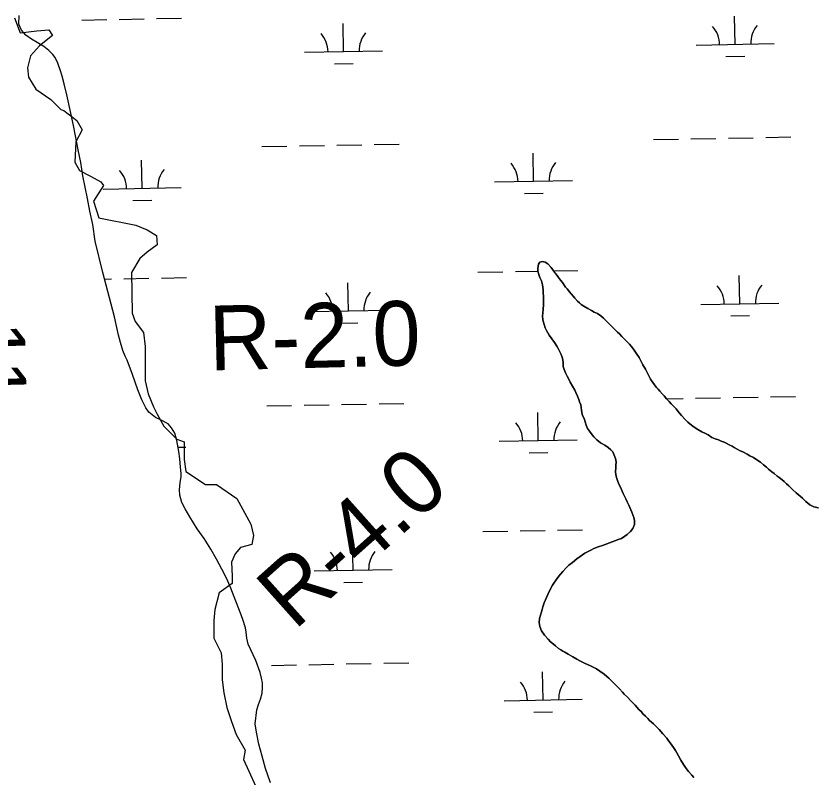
# Model space of a CAD drawing. Extents: x 3925854 to 3964121, y 224593 to 250589.
# Drawn here: x 3946690 to 3947714, y 239589 to 240565 of the extents above; entities that cross this region are included whole.
import ezdxf

# ---------------------------------------------------------------- set-up
doc = ezdxf.new("R2010")
doc.units = 0
for name, color, linetype in [('V-RIVR-EDGE', 7, 'Continuous'), ('V-RIVR-RANG', 7, 'Continuous'), ('V-RIVR-RANG-IDEN', 7, 'Continuous'), ('V-TOPO-SHOR', 7, 'Continuous'), ('V-WETL-SWMP', 7, 'Continuous')]:
    doc.layers.add(name, color=color, linetype=linetype)

msp = doc.modelspace()

# ---------------------------------------------------------------- linework, layer by layer
at = {"layer": 'V-RIVR-EDGE'}
msp.add_lwpolyline([(3946688.345, 240562.693), (3946695.468, 240543.697), (3946716.838, 240546.072), (3946732.272, 240547.259), (3946737.02, 240540.136), (3946720.399, 240527.076), (3946708.527, 240514.017), (3946704.966, 240498.583), (3946706.153, 240486.711), (3946715.651, 240471.277), (3946734.646, 240458.218), (3946747.705, 240445.159), (3946751.267, 240443.971), (3946767.888, 240430.912), (3946775.011, 240419.04), (3946766.701, 240403.606), (3946765.514, 240377.488), (3946771.45, 240366.803), (3946785.696, 240359.679), (3946798.755, 240352.556), (3946802.317, 240347.807), (3946789.258, 240327.625), (3946796.381, 240306.255), (3946843.87, 240296.757), (3946858.116, 240290.821), (3946869.988, 240283.698), (3946871.175, 240271.826), (3946858.116, 240262.328), (3946848.618, 240254.017), (3946837.934, 240236.209), (3946839.121, 240183.972), (3946842.682, 240173.287), (3946853.367, 240159.04), (3946855.742, 240141.232), (3946855.742, 240130.547), (3946855.742, 240113.926), (3946855.742, 240097.305), (3946859.303, 240080.684), (3946866.427, 240064.063), (3946871.175, 240054.566), (3946879.486, 240039.132), (3946896.107, 240022.511), (3946905.605, 240018.949), (3946905.605, 239996.392), (3946907.979, 239980.959), (3946932.911, 239964.338), (3946947.157, 239964.338), (3946973.276, 239946.529), (3946991.084, 239913.287), (3946994.646, 239899.041), (3946992.271, 239887.169), (3946978.025, 239883.607), (3946970.901, 239875.297), (3946966.152, 239864.612), (3946967.34, 239846.804), (3946967.34, 239837.306), (3946950.719, 239825.434), (3946944.783, 239804.064), (3946943.595, 239789.817), (3946943.595, 239767.26), (3946953.093, 239748.265), (3946954.28, 239734.018), (3946954.28, 239713.836), (3946956.655, 239697.215), (3946960.216, 239678.219), (3946966.152, 239660.411), (3946972.089, 239643.79), (3946983.961, 239623.608), (3946981.586, 239611.735), (3947004.143, 239561.872)], dxfattribs=at)
at = {"layer": 'V-TOPO-SHOR'}
for points in [[(3947380.129, 240146.521), (3947376.953, 240151.293), (3947373.369, 240155.97), (3947370, 240161.653), (3947368.421, 240165.201), (3947367.055, 240169.653), (3947365.3, 240175.42), (3947364.849, 240180.569), (3947365.187, 240183.995), (3947365.947, 240189.232), (3947366.41, 240194.874), (3947366.166, 240200.527), (3947366.117, 240205.671), (3947365.763, 240210.314), (3947365.701, 240214.047), (3947364.96, 240220.308), (3947363.602, 240225.567), (3947361.628, 240229.823), (3947360.055, 240233.673), (3947359.088, 240237.819), (3947359.025, 240241.249), (3947359.787, 240246.688), (3947361.529, 240249.494), (3947365.169, 240250.262), (3947368.589, 240249.32), (3947371.997, 240247.266), (3947376.087, 240242.787), (3947379.167, 240238.417), (3947380.957, 240235.977), (3947383.742, 240232.217), (3947385.634, 240229.776), (3947388.121, 240226.421), (3947390.509, 240223.272), (3947394.484, 240217.58), (3947396.374, 240215.041), (3947399.463, 240211.377), (3947401.558, 240209.036), (3947404.546, 240205.475), (3947406.538, 240203.134), (3947409.932, 240199.568), (3947412.328, 240197.223), (3947414.728, 240195.282), (3947417.933, 240193.031), (3947422.945, 240189.953), (3947427.659, 240187.483), (3947431.27, 240185.527), (3947435.485, 240183.467), (3947439.589, 240180.6), (3947442.989, 240177.54), (3947445.983, 240174.582), (3947450.275, 240170.302), (3947455.168, 240165.512), (3947457.564, 240163.167), (3947461.261, 240159.698), (3947463.559, 240157.455), (3947466.651, 240154.197), (3947471.741, 240148.999), (3947476.332, 240144.311), (3947478.624, 240141.565), (3947481.512, 240137.903), (3947485.19, 240132.822), (3947488.661, 240127.136), (3947491.827, 240121.154), (3947493.607, 240117.808), (3947496.976, 240112.022), (3947500.339, 240105.532), (3947503.603, 240099.445), (3947506.485, 240095.079), (3947508.67, 240091.929), (3947511.058, 240088.777), (3947513.151, 240086.437), (3947515.146, 240084.096), (3947518.636, 240080.227), (3947520.729, 240077.886), (3947523.92, 240074.22), (3947527.512, 240070.552), (3947530.004, 240067.804), (3947533.697, 240063.833), (3947536.291, 240061.183), (3947538.483, 240058.537), (3947540.473, 240055.995), (3947543.263, 240052.636), (3947548.051, 240047.445), (3947551.045, 240044.387), (3947553.644, 240042.14), (3947557.748, 240039.072), (3947560.452, 240037.129), (3947563.858, 240034.872), (3947569.371, 240031.689), (3947574.089, 240029.523), (3947577.2, 240027.976), (3947581.907, 240024.599), (3947586.328, 240023.041), (3947590.447, 240021.484), (3947594.164, 240019.934), (3947597.781, 240018.584), (3947600.488, 240017.245), (3947604.201, 240015.391), (3947608.215, 240013.331), (3947610.82, 240011.693)], [(3947372.171, 239766.121), (3947367.581, 239771.11), (3947363.707, 239776.799), (3947361.441, 239782.069), (3947360.79, 239787.32), (3947361.046, 239792.563), (3947362.197, 239796.585), (3947363.557, 239801.109), (3947364.495, 239804.226), (3947365.439, 239807.646), (3947367.006, 239812.775), (3947369.998, 239819.3), (3947371.753, 239823.215), (3947374.846, 239829.638), (3947377.928, 239835.053), (3947379.57, 239837.758), (3947382.542, 239842.268), (3947385.915, 239846.569), (3947388.059, 239849.17), (3947391.123, 239852.87), (3947395.307, 239857.466), (3947398.873, 239860.757), (3947403.346, 239864.243), (3947409.041, 239868.822), (3947413.11, 239872.009), (3947416.156, 239873.993), (3947419.203, 239876.08), (3947422.552, 239877.962), (3947427.623, 239880.631), (3947430.969, 239882.312), (3947436.236, 239884.477), (3947441.803, 239886.234), (3947445.346, 239887.508), (3947450.714, 239889.573), (3947454.154, 239890.746), (3947459.115, 239892.509), (3947462.154, 239893.689), (3947466.305, 239895.26), (3947470.469, 239897.941), (3947473.418, 239900.228), (3947477.69, 239903.917), (3947480.76, 239908.021), (3947482.929, 239912.84), (3947482.984, 239918.286), (3947482.114, 239921.927), (3947479.466, 239929.015), (3947478.124, 239931.993), (3947476.783, 239934.852), (3947475.423, 239937.973), (3947473.567, 239942.046), (3947471.812, 239945.796), (3947468.515, 239952.749), (3947467.276, 239955.85), (3947464.845, 239960.716), (3947463.405, 239963.917), (3947461.634, 239968.072), (3947459.872, 239973.354), (3947458.904, 239977.139), (3947458.455, 239980.653), (3947458.93, 239985.53), (3947459.166, 239988.714), (3947459.434, 239993.291), (3947458.674, 239997.838), (3947456.923, 240002.133), (3947454.988, 240006.085), (3947452.676, 240008.733), (3947449.256, 240011.592), (3947444.99, 240014.662), (3947439.356, 240017.929), (3947434.594, 240021.812), (3947430.639, 240025.584), (3947428.487, 240028.046), (3947425.065, 240032.601), (3947422.681, 240036.277), (3947420.747, 240040.535), (3947419.601, 240044.541), (3947418.454, 240048.788), (3947416.277, 240052.845), (3947415.406, 240056.485), (3947415.036, 240059.516), (3947414.667, 240062.948), (3947413.895, 240066.387), (3947412.523, 240070.132), (3947411.646, 240073.168), (3947409.877, 240077.522), (3947407.603, 240082.187), (3947406.223, 240085.226), (3947403.452, 240090.399), (3947400.583, 240095.673), (3947398.207, 240100.136), (3947396.425, 240103.281), (3947394.351, 240107.539), (3947392.68, 240111.59), (3947391.512, 240115.84), (3947391.26, 240120.683), (3947390.41, 240126.239), (3947388.743, 240130.897), (3947387.265, 240134.241), (3947384.891, 240138.806), (3947383.308, 240141.747), (3947380.129, 240146.521)], [(3947610.82, 240011.693), (3947614.431, 240009.536), (3947617.64, 240007.89), (3947622.459, 240005.721), (3947627.274, 240003.048), (3947630.684, 240001.197), (3947635.501, 239998.827), (3947639.81, 239996.161), (3947644.418, 239993.087), (3947648.415, 239989.515), (3947652.214, 239986.349), (3947654.813, 239984.102), (3947659.014, 239980.631), (3947661.713, 239978.382), (3947665.717, 239975.214), (3947668.217, 239973.172), (3947672.119, 239970.104), (3947674.517, 239968.062), (3947677.819, 239965.306), (3947680.915, 239962.549), (3947686.011, 239957.654), (3947690.104, 239953.779), (3947695.102, 239949.391), (3947698.1, 239946.636), (3947702.696, 239942.352), (3947707.697, 239938.266), (3947712.714, 239935.894), (3947718.647, 239934.219)], [(3947559.147, 239588.779), (3947556.556, 239591.63), (3947552.168, 239596.416), (3947548.086, 239601.601), (3947545.7, 239605.056), (3947542.13, 239610.942), (3947539.261, 239616.421), (3947537.082, 239620.275), (3947535.601, 239623.216), (3947532.818, 239627.179), (3947528.64, 239632.87), (3947526.748, 239635.209), (3947524.163, 239638.867), (3947519.381, 239644.667), (3947514.394, 239650.063), (3947511.402, 239653.221), (3947507.208, 239657.198), (3947502.213, 239661.89), (3947499.915, 239664.032), (3947496.82, 239667.09), (3947493.726, 239670.248), (3947491.733, 239672.589), (3947488.641, 239675.95), (3947483.654, 239681.348), (3947478.462, 239686.646), (3947473.373, 239691.844), (3947469.781, 239695.512), (3947467.384, 239697.958), (3947463.495, 239702.234), (3947458.707, 239707.327), (3947453.417, 239712.728), (3947449.821, 239715.992), (3947447.521, 239717.934), (3947443.82, 239720.998), (3947438.616, 239725.085), (3947434.109, 239727.957), (3947429.994, 239730.017), (3947427.287, 239731.457), (3947422.666, 239733.423), (3947419.756, 239734.965), (3947415.541, 239736.925), (3947412.832, 239738.264), (3947409.019, 239740.22), (3947403.808, 239743.501), (3947397.791, 239746.893), (3947393.679, 239749.156), (3947390.972, 239750.696), (3947388.366, 239752.336), (3947385.563, 239754.181), (3947381.561, 239757.35), (3947378.86, 239759.596), (3947375.362, 239762.76), (3947372.171, 239766.121)]]:
    msp.add_lwpolyline(points, dxfattribs=at)
at = {"layer": 'V-WETL-SWMP'}
for p, q in [((3946774.397, 240559.968), (3946806.392, 240560.55)), ((3946822.389, 240560.841), (3946854.384, 240561.423)), ((3946870.381, 240561.714), (3946902.376, 240562.295)), ((3947611.855, 240528.758), (3947611.2, 240564.752)), ((3947110.03, 240519.633), (3947109.375, 240555.627)), ((3947561.863, 240527.849), (3947661.846, 240529.667)), ((3947060.038, 240518.724), (3947160.021, 240520.542)), ((3947600.137, 240513.112), (3947624.133, 240513.548)), ((3947098.312, 240503.987), (3947122.308, 240504.423)), ((3947507.211, 240406.765), (3947539.206, 240407.346)), ((3947555.203, 240407.637), (3947587.198, 240408.219)), ((3947603.195, 240408.51), (3947635.19, 240409.092)), ((3947651.187, 240409.382), (3947683.182, 240409.964)), ((3947005.386, 240397.64), (3947037.381, 240398.222)), ((3947053.378, 240398.512), (3947085.373, 240399.094)), ((3947101.37, 240399.385), (3947133.365, 240399.967)), ((3947149.362, 240400.258), (3947181.357, 240400.84)), ((3947353.567, 240353.22), (3947352.913, 240389.215)), ((3946851.742, 240344.096), (3946851.088, 240380.09)), ((3947303.576, 240352.311), (3947403.559, 240354.129)), ((3946801.75, 240343.187), (3946901.734, 240345.005)), ((3947341.85, 240337.574), (3947365.846, 240338.01)), ((3946840.025, 240328.449), (3946864.021, 240328.885)), ((3947379.299, 240238.237), (3947410.249, 240238.8)), ((3946828.437, 240228.221), (3946860.432, 240228.803)), ((3946876.429, 240229.094), (3946908.424, 240229.675)), ((3947282.27, 240236.473), (3947314.265, 240237.055)), ((3947330.262, 240237.346), (3947359.088, 240237.87)), ((3947617.903, 240196.138), (3947617.248, 240232.132)), ((3946803.547, 240227.768), (3946812.44, 240227.93)), ((3947116.078, 240187.013), (3947115.423, 240223.007)), ((3947066.086, 240186.104), (3947166.069, 240187.922)), ((3947567.911, 240195.229), (3947667.894, 240197.047)), ((3947606.185, 240180.492), (3947630.181, 240180.928)), ((3947104.36, 240171.367), (3947128.356, 240171.803)), ((3947523.818, 240074.337), (3947545.254, 240074.726)), ((3947561.251, 240075.017), (3947593.246, 240075.599)), ((3947609.243, 240075.89), (3947641.238, 240076.472)), ((3947657.235, 240076.762), (3947689.23, 240077.344)), ((3947011.434, 240065.02), (3947043.429, 240065.602)), ((3947059.426, 240065.892), (3947091.421, 240066.474)), ((3947107.418, 240066.765), (3947139.413, 240067.347)), ((3947155.41, 240067.638), (3947187.405, 240068.22)), ((3947359.615, 240020.6), (3947358.961, 240056.594)), ((3947309.624, 240019.691), (3947409.607, 240021.509)), ((3946897.948, 240012.206), (3946907.782, 240012.385)), ((3947347.898, 240004.954), (3947371.894, 240005.39)), ((3947288.318, 239903.853), (3947320.313, 239904.435)), ((3947336.31, 239904.726), (3947368.305, 239905.307)), ((3947384.302, 239905.598), (3947416.297, 239906.18)), ((3947122.126, 239854.393), (3947121.471, 239890.387)), ((3947072.134, 239853.484), (3947172.117, 239855.302)), ((3947110.408, 239838.747), (3947134.404, 239839.183)), ((3947017.482, 239732.4), (3947049.477, 239732.982)), ((3947065.474, 239733.272), (3947097.469, 239733.854)), ((3947113.466, 239734.145), (3947145.461, 239734.727)), ((3947161.459, 239735.018), (3947193.453, 239735.599)), ((3947365.663, 239687.98), (3947365.009, 239723.974)), ((3947315.672, 239687.071), (3947415.655, 239688.889)), ((3947353.946, 239672.334), (3947377.942, 239672.77))]:
    msp.add_line(p, q, dxfattribs=at)
for points in [[(3946851.302, 240073.029), (3946846.392, 240085.889), (3946839.33, 240105.228), (3946832.461, 240123.656), (3946829.995, 240129.028), (3946827.142, 240136.017), (3946824.023, 240146.438), (3946821.397, 240155.846), (3946816.397, 240179.399), (3946801.35, 240236.039), (3946791.479, 240276.286), (3946788.374, 240297.802), (3946784.918, 240314.682), (3946781.557, 240330.956), (3946778.58, 240345.411), (3946775.909, 240360.165), (3946773.163, 240377.441), (3946769.699, 240393.615), (3946764.149, 240422.52), (3946759.92, 240442.636), (3946755.401, 240464.066), (3946751.915, 240478.022), (3946749.193, 240487.834), (3946746.947, 240495.018), (3946743.721, 240504.836), (3946740.464, 240511.728), (3946737.377, 240515.593), (3946732.286, 240520.689), (3946725.887, 240526.101), (3946717.064, 240531.236), (3946709.843, 240535.245), (3946702.736, 240540.463), (3946696.952, 240546.877), (3946693.805, 240554.676), (3946694.124, 240565.97)], [(3947610.821, 240011.692), (3947608.215, 240013.332), (3947604.202, 240015.391), (3947600.489, 240017.245), (3947597.78, 240018.585), (3947594.163, 240019.934), (3947590.447, 240021.485), (3947586.328, 240023.041), (3947581.906, 240024.6), (3947577.2, 240027.977), (3947574.089, 240029.522), (3947569.371, 240031.689), (3947563.857, 240034.873), (3947560.451, 240037.128), (3947557.748, 240039.072), (3947553.644, 240042.141), (3947551.045, 240044.387), (3947548.051, 240047.444), (3947543.263, 240052.637), (3947540.474, 240055.995), (3947538.483, 240058.537), (3947536.291, 240061.182), (3947533.696, 240063.832), (3947530.005, 240067.804), (3947527.512, 240070.553), (3947523.919, 240074.221), (3947520.729, 240077.886), (3947518.636, 240080.227), (3947515.145, 240084.096), (3947513.152, 240086.437), (3947511.059, 240088.778), (3947508.671, 240091.93), (3947506.484, 240095.079), (3947503.604, 240099.446), (3947500.339, 240105.532), (3947496.977, 240112.022), (3947493.608, 240117.807), (3947491.827, 240121.154), (3947488.661, 240127.137), (3947485.19, 240132.822), (3947481.511, 240137.903), (3947478.623, 240141.564), (3947476.332, 240144.311), (3947471.741, 240148.999), (3947466.651, 240154.196), (3947463.558, 240157.456), (3947461.261, 240159.698), (3947457.565, 240163.166), (3947455.169, 240165.511), (3947450.276, 240170.302), (3947445.983, 240174.583), (3947442.988, 240177.539), (3947439.59, 240180.6), (3947435.485, 240183.467), (3947431.27, 240185.528), (3947427.659, 240187.482), (3947422.944, 240189.952), (3947417.933, 240193.03), (3947414.728, 240195.282), (3947412.328, 240197.223), (3947409.931, 240199.568), (3947406.539, 240203.133), (3947404.546, 240205.474), (3947401.557, 240209.035), (3947399.463, 240211.377), (3947396.374, 240215.04), (3947394.484, 240217.581), (3947390.509, 240223.271), (3947388.12, 240226.422), (3947385.634, 240229.777), (3947383.743, 240232.217), (3947380.957, 240235.978), (3947379.167, 240238.417), (3947376.086, 240242.787), (3947371.997, 240247.267), (3947368.589, 240249.32), (3947365.169, 240250.263), (3947361.53, 240249.494), (3947359.786, 240246.688), (3947359.024, 240241.249), (3947359.089, 240237.819), (3947360.054, 240233.673), (3947361.628, 240229.824), (3947363.602, 240225.567), (3947364.959, 240220.308), (3947365.701, 240214.047), (3947365.763, 240210.314), (3947366.118, 240205.671), (3947366.166, 240200.526), (3947366.41, 240194.875), (3947365.948, 240189.232), (3947365.188, 240183.995), (3947364.849, 240180.569), (3947365.3, 240175.42), (3947367.056, 240169.653), (3947368.422, 240165.2), (3947369.999, 240161.654), (3947373.369, 240155.97), (3947376.952, 240151.293), (3947380.13, 240146.52), (3947383.308, 240141.746)], [(3947383.308, 240141.746), (3947384.892, 240138.805), (3947387.265, 240134.241), (3947388.743, 240130.897), (3947390.41, 240126.24), (3947391.26, 240120.684), (3947391.512, 240115.84), (3947392.679, 240111.591), (3947394.351, 240107.539), (3947396.425, 240103.282), (3947398.208, 240100.136), (3947400.583, 240095.674), (3947403.453, 240090.399), (3947406.223, 240085.226), (3947407.604, 240082.186), (3947409.876, 240077.522), (3947411.646, 240073.167), (3947412.522, 240070.132), (3947413.895, 240066.386), (3947414.667, 240062.948), (3947415.035, 240059.515), (3947415.407, 240056.485), (3947416.277, 240052.845), (3947418.454, 240048.788), (3947419.6, 240044.54), (3947420.748, 240040.534), (3947422.681, 240036.277), (3947425.064, 240032.601), (3947428.486, 240028.047), (3947430.639, 240025.584), (3947434.594, 240021.811), (3947439.355, 240017.929), (3947444.99, 240014.663), (3947449.255, 240011.592), (3947452.675, 240008.733), (3947454.988, 240006.086), (3947456.923, 240002.132), (3947458.674, 239997.838), (3947459.434, 239993.291), (3947459.165, 239988.714), (3947458.93, 239985.53), (3947458.456, 239980.653), (3947458.903, 239977.138), (3947459.873, 239973.355), (3947461.634, 239968.072), (3947463.406, 239963.918), (3947464.845, 239960.716), (3947467.276, 239955.849), (3947468.515, 239952.75), (3947471.812, 239945.796), (3947473.568, 239942.046), (3947475.422, 239937.972), (3947476.782, 239934.852), (3947478.124, 239931.993), (3947479.465, 239929.014), (3947482.114, 239921.926), (3947482.984, 239918.286), (3947482.928, 239912.84), (3947480.76, 239908.021), (3947477.691, 239903.917), (3947473.417, 239900.229), (3947470.468, 239897.94), (3947466.305, 239895.26), (3947462.153, 239893.689), (3947459.115, 239892.51), (3947454.154, 239890.746), (3947450.713, 239889.572), (3947445.345, 239887.509), (3947441.802, 239886.235), (3947436.236, 239884.477), (3947430.969, 239882.312), (3947427.623, 239880.632), (3947422.552, 239877.962), (3947419.204, 239876.08), (3947416.156, 239873.993), (3947413.11, 239872.008), (3947409.042, 239868.822), (3947403.346, 239864.242), (3947398.872, 239860.758), (3947395.307, 239857.466), (3947391.124, 239852.87), (3947388.06, 239849.17), (3947385.915, 239846.569), (3947382.542, 239842.267), (3947379.57, 239837.759), (3947377.928, 239835.053), (3947374.846, 239829.638), (3947371.753, 239823.215), (3947369.998, 239819.299), (3947367.005, 239812.774), (3947365.439, 239807.646), (3947364.496, 239804.227), (3947363.556, 239801.11), (3947362.198, 239796.585), (3947361.046, 239792.562), (3947360.79, 239787.32), (3947361.442, 239782.068), (3947363.707, 239776.8), (3947367.582, 239771.111), (3947372.17, 239766.121), (3947375.362, 239762.76)], [(3947016.181, 239581.642), (3947009.716, 239600.167), (3947005.544, 239616.046), (3947001.262, 239631.119), (3946998.298, 239646.784), (3946996.795, 239657.491), (3946998.896, 239675.322), (3947000.987, 239682.361), (3947003.578, 239689.092), (3947005.475, 239696.94), (3947006.153, 239703.993), (3947005.914, 239710.048), (3947004.968, 239716.109), (3947003.024, 239723.19), (3946997.637, 239738.678), (3946987.483, 239759.36), (3946985.849, 239767.143), (3946985.324, 239774.915), (3946984.375, 239780.674), (3946980.954, 239791.2), (3946976.534, 239802.643), (3946971.717, 239814.696), (3946965.534, 239831.201), (3946960.213, 239843.36), (3946954.088, 239855.729), (3946947.161, 239868.611), (3946939.63, 239881.6), (3946931.094, 239894.901), (3946922.245, 239907.299), (3946912.825, 239922.929), (3946906.979, 239933.077), (3946902.829, 239941.39), (3946900.201, 239950.496), (3946899.769, 239957.561), (3946900.672, 239966.73), (3946901.756, 239974.082), (3946901.8, 239978.318), (3946900.877, 239986.497), (3946900.082, 239997.399), (3946898.968, 240006.69), (3946896.389, 240020.636), (3946893.581, 240029.985), (3946889.539, 240037.047), (3946885.015, 240042.298), (3946876.184, 240046.707), (3946868.857, 240050.132), (3946860.515, 240056.896), (3946856.44, 240062.788), (3946851.302, 240073.029)], [(3947718.648, 239934.219), (3947712.715, 239935.894), (3947707.696, 239938.266), (3947702.695, 239942.352), (3947698.1, 239946.636), (3947695.102, 239949.391), (3947690.105, 239953.78), (3947686.01, 239957.655), (3947680.916, 239962.549), (3947677.818, 239965.305), (3947674.518, 239968.063), (3947672.119, 239970.105), (3947668.217, 239973.171), (3947665.716, 239975.214), (3947661.714, 239978.383), (3947659.014, 239980.63), (3947654.814, 239984.103), (3947652.215, 239986.349), (3947648.415, 239989.515), (3947644.417, 239993.087), (3947639.81, 239996.16), (3947635.5, 239998.828), (3947630.683, 240001.197), (3947627.273, 240003.048), (3947622.459, 240005.721), (3947617.64, 240007.889), (3947614.43, 240009.536), (3947610.821, 240011.692)], [(3947375.362, 239762.76), (3947378.86, 239759.596), (3947381.56, 239757.349), (3947385.562, 239754.181), (3947388.367, 239752.336), (3947390.972, 239750.696), (3947393.68, 239749.155), (3947397.792, 239746.893), (3947403.808, 239743.502), (3947409.019, 239740.22), (3947412.832, 239738.264), (3947415.541, 239736.925), (3947419.757, 239734.965), (3947422.666, 239733.422), (3947427.286, 239731.457), (3947429.994, 239730.017), (3947434.108, 239727.957), (3947438.617, 239725.086), (3947443.82, 239720.998), (3947447.52, 239717.933), (3947449.82, 239715.993), (3947453.417, 239712.728), (3947458.707, 239707.327), (3947463.495, 239702.234), (3947467.385, 239697.958), (3947469.78, 239695.512), (3947473.373, 239691.844), (3947478.463, 239686.647), (3947483.653, 239681.348), (3947488.641, 239675.95), (3947491.733, 239672.59), (3947493.726, 239670.249), (3947496.82, 239667.09), (3947499.915, 239664.032), (3947502.212, 239661.89), (3947507.207, 239657.199), (3947511.402, 239653.222), (3947514.395, 239650.064), (3947519.382, 239644.666), (3947524.164, 239638.867), (3947526.748, 239635.209), (3947528.64, 239632.87), (3947532.818, 239627.178), (3947535.601, 239623.216), (3947537.083, 239620.275), (3947539.262, 239616.42), (3947542.131, 239610.943), (3947545.701, 239605.056), (3947548.085, 239601.602), (3947552.167, 239596.415), (3947556.556, 239591.629), (3947559.148, 239588.778)]]:
    msp.add_lwpolyline(points, dxfattribs=at)
for centre, start, end in [((3947556.612, 240528.229), 0.269879, 41.813537), ((3947667.08, 240530.237), 140.269876, 181.813534), ((3947054.787, 240519.104), 0.269879, 41.813537), ((3947165.255, 240521.112), 140.269876, 181.813534), ((3947298.325, 240352.691), 0.269879, 41.813537), ((3947408.792, 240354.7), 140.269876, 181.813534), ((3946796.5, 240343.566), 0.269879, 41.813537), ((3946906.967, 240345.575), 140.269876, 181.813534), ((3947562.66, 240195.609), 0.269879, 41.813537), ((3947673.128, 240197.617), 140.269876, 181.813534), ((3947060.835, 240186.484), 0.269879, 41.813537), ((3947171.303, 240188.492), 140.269876, 181.813534), ((3947414.841, 240022.079), 140.269876, 181.813534), ((3947304.373, 240020.071), 0.269879, 41.813537), ((3947066.883, 239853.864), 0.269879, 41.813537), ((3947177.351, 239855.872), 140.269876, 181.813534), ((3947310.421, 239687.451), 0.269879, 41.813537), ((3947420.889, 239689.459), 140.269876, 181.813534)]:
    msp.add_arc(centre, 35.246, start, end, dxfattribs=at)

# ---------------------------------------------------------------- texts
at = {"layer": 'V-RIVR-RANG'}
msp.add_text('-11', height=67, rotation=271.447, dxfattribs=at).set_placement((3946633.502, 240201.024))
at = {"layer": 'V-RIVR-RANG-IDEN'}
for s, rotation, p in [('R-2.0', 1.446922, (3946938.321, 240110.513)), ('R-4.0', 41.76307, (3947046.822, 239776.236))]:
    msp.add_text(s, height=83, rotation=rotation, dxfattribs=at).set_placement(p)

doc.saveas('drawing.dxf')
